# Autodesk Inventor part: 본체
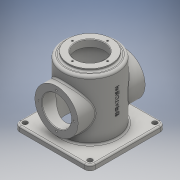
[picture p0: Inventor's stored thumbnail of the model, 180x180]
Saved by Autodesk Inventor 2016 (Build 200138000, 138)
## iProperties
Created: 2019-08
Part Number: 본체
Material: 일반
Document SubType Name: Modeling
Designer: user
Density: 1 g/cm^3
Appearance: 기본값
Mass: 414.921 g
Surface Area: 1160.05 cm^2
Volume: 414.921 cm^3
Author: user
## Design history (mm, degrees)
sketch "스케치1"
  geometry: L1 (70, -70)-(-70, -70); L2 (-70, -70)-(-70, 70); L3 (-70, 70)-(70, 70); L4 (70, 70)-(70, -70); L5 (70, -70)-(-70, 70); L6 (-70, -70)-(70, 70); 1 further point
  constraints: 12 end point, 2 midpoint, 2 parallel, 1 horizontal, 1 perpendicular
  dimensions: "d0" = 140 distance of L2.end L3.end; "d1" = 140 distance of L1.end L2.end
extrude "돌출1" new body sketch "스케치1" distance "d2" = 10; taper "d3" = 0 deg
sketch "스케치2"
  geometry: C1 r 50 at (0, 0); 1 further point
  constraints: 1 centre point, 1 coincident
  dimensions: "d4" = 100 diameter of C1
extrude "돌출2" join sketch "스케치2" distance "d5" = 110; taper "d6" = 0 deg
sketch "스케치3"
  geometry: C1 r 45 at (0, 0); 1 further point
  constraints: 1 centre point, 1 coincident
  dimensions: "d7" = 90 diameter of C1
extrude "돌출3" cut sketch "스케치3" distance "d8" = 112; taper "d9" = 0 deg
sketch "스케치4"
  geometry: C1 r 40 at (0, 0); 1 further point
  constraints: 1 centre point, 1 coincident
  dimensions: "d10" = 80 diameter of C1
extrude "돌출4" join sketch "스케치4" distance "d11" = 5; taper "d12" = 0 deg
node "작업 평면1"
sketch "스케치6"
  geometry: L1 (-70, 0)-(70, 0) reference; C1 r 40 at (0, 60); 2 further points
  constraints: 1 centre point, 1 midpoint, 1 vertical alignment
  dimensions: "d14" = 80 diameter of C1; "d15" = 60 distance from line of L1 C1.centre
extrude "돌출5" join sketch "스케치6" stored distance "d16" = 5; taper "d17" = 0 deg
hole "구멍1" diameter "d20" = 54; stored, may be unused: countersink angle "d24" = 90 deg, drill point angle "d26" = 118 deg; dims "d18" = 10, "d19" = 10, "d21" = 6, "d22" = 4, "d23" = 2, "d25" = 8
sketch "스케치7"
  geometry: C1 r 27 at (0, 0); 1 further point
  constraints: 1 centre point, 1 coincident
  dimensions: "d27" = 54 diameter of C1
extrude "돌출6" cut sketch "스케치7" distance "d28" = 13; taper "d29" = 0 deg
fillet "모깎기1" dims "d30" = 5
sketch "스케치8"
  geometry: 2 further points
  constraints: 1 vertical alignment
  dimensions: "d31" = 32.5 distance of point (0, 0) point (0, 32.5)
hole "구멍2" sketch "스케치8" at (0, 32.5) diameter "d32" = 3.242; stored, may be unused: countersink angle "d36" = 90 deg, drill point angle "d38" = 118 deg; dims "d33" = 8, "d34" = 4, "d35" = 2, "d37" = 10
sketch "스케치9"
  geometry: C1 r 27 at (0, 0) reference; 2 further points
  constraints: 1 vertical alignment
  dimensions: "d42" = 32.5 distance of C1.centre point (0, 32.5)
hole "구멍3" sketch "스케치9" at (0, 32.5) diameter "d43" = 3.242; stored, may be unused: countersink angle "d47" = 90 deg, drill point angle "d49" = 118 deg; dims "d44" = 8, "d45" = 4, "d46" = 2, "d48" = 10
chamfer "모따기1" distance "d53" = 1; stored, may be unused: second distance "d54" = 2, angle "d55" = 45 deg
chamfer "모따기2" distance "d56" = 1; stored, may be unused: second distance "d57" = 2, angle "d58" = 45 deg
fillet "모깎기2" dims "d59" = 10
hole "구멍4" diameter "d62" = 9; stored, may be unused: countersink angle "d66" = 90 deg, drill point angle "d68" = 0 deg; dims "d60" = 10, "d61" = 10, "d63" = 8, "d64" = 4, "d65" = 2, "d67" = 10
hole "구멍5" diameter "d71" = 9; stored, may be unused: countersink angle "d75" = 90 deg, drill point angle "d77" = 0 deg; dims "d69" = 10, "d70" = 10, "d72" = 8, "d73" = 4, "d74" = 2, "d76" = 10
fillet "모깎기3" dims "d78" = 3
fillet "모깎기4" dims "d79" = 3
fillet "모깎기5" dims "d80" = 3
fillet "모깎기6" dims "d81" = 3
node "작업 평면2"
sketch "스케치13" dims "d0" = 140, "d1" = 140, "d10" = 80
  geometry: L1 (60, 0)-(-60, 0) reference; 3 further points
  constraints: 1 midpoint, 1 vertical alignment, 1 other
  dimensions: "d83" = 70 distance from line of L1 point (0, 70)
feature "엠보싱1" sketch "스케치13" dims "d10" = 80, "d84" = 0.5, "d85" = 0
fillet "모깎기7" dims "d86" = 3
node "솔리드1"
mirror "대칭1"
pattern_circular "원형 패턴1" dims angle "d40" = 360 deg
pattern_circular "원형 패턴2" dims angle "d51" = 360 deg
mirror "대칭2"
mirror "대칭3"
other parameters: "d13" = -62, "d82" = 54.25
